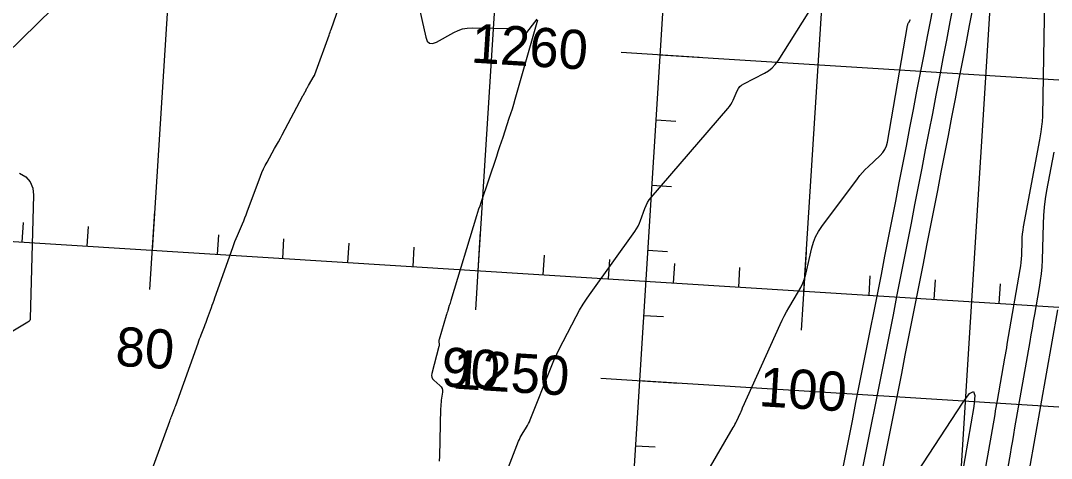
# Model space of a CAD drawing. Extents: x 658976 to 668721, y 639543 to 647196.
# Drawn here: x 661529.7 to 661687.6, y 641890.7 to 641957.7 of the extents above; entities that cross this region are included whole.
import ezdxf

# ---------------------------------------------------------------- set-up
doc = ezdxf.new("R2010")
doc.units = 0
for name, color, linetype in [('Ex_Minor Contours', 7, 'Continuous'), ('R_Axis', 7, 'Continuous'), ('R_Axis Annot', 7, 'Continuous'), ('R_Grid', 7, 'Continuous'), ('R_Water', 7, 'Continuous')]:
    doc.layers.add(name, color=color, linetype=linetype)

msp = doc.modelspace()

# ---------------------------------------------------------------- linework, layer by layer
at = {"layer": 'Ex_Minor Contours'}
for points in [[(661686.69, 641967.13), (661686.26, 641943.13), (661686.25, 641942.82), (661686.23, 641942.51), (661686.2, 641942.21), (661686.16, 641941.9), (661685.99, 641940.68), (661685.94, 641940.38), (661685.89, 641940.07), (661685.84, 641939.77), (661685.79, 641939.47), (661683.33, 641926.15), (661683.24, 641925.61), (661683.17, 641925.07), (661683.12, 641924.52), (661683.1, 641923.97), (661683.03, 641921.78), (661683, 641921.23), (661682.96, 641920.68), (661682.89, 641920.14), (661682.81, 641919.6), (661680.82, 641908.15), (661680.73, 641907.61), (661680.64, 641907.08), (661680.54, 641906.54), (661680.45, 641906.01), (661679.31, 641899.55), (661679.22, 641899.01), (661679.12, 641898.47), (661679.03, 641897.93), (661678.94, 641897.38), (661677.04, 641886.44)], [(661589.69, 641964.5), (661591.78, 641955.18), (661592, 641954.58), (661592.35, 641954.26), (661592.83, 641954.21), (661593.42, 641954.44), (661596.06, 641955.9), (661596.73, 641956.22), (661597.42, 641956.44), (661598.14, 641956.57), (661598.88, 641956.61), (661605.15, 641956.51), (661605.28, 641956.5), (661605.41, 641956.49), (661605.54, 641956.47), (661605.67, 641956.44), (661606.17, 641956.3), (661606.29, 641956.26), (661606.38, 641956.19), (661606.46, 641956.1), (661606.51, 641955.99), (661606.68, 641955.48), (661606.72, 641955.38), (661606.78, 641955.34), (661606.85, 641955.36), (661606.92, 641955.44), (661608.84, 641957.93)], [(661548.16, 641884.36), (661552.57, 641896.38), (661552.64, 641896.58), (661552.72, 641896.78), (661552.79, 641896.98), (661552.87, 641897.18), (661553.18, 641897.98), (661553.26, 641898.17), (661553.34, 641898.37), (661553.41, 641898.57), (661553.48, 641898.77), (661556.9, 641908.34), (661557.02, 641908.66), (661557.13, 641908.98), (661557.26, 641909.29), (661557.38, 641909.61), (661557.88, 641910.87), (661558, 641911.19), (661558.13, 641911.51), (661558.24, 641911.82), (661558.36, 641912.14), (661558.94, 641913.76), (661559.08, 641914.13), (661559.21, 641914.51), (661559.35, 641914.88), (661559.48, 641915.26), (661562.21, 641922.97), (661562.38, 641923.44), (661562.55, 641923.9), (661562.74, 641924.35), (661562.93, 641924.81), (661563.7, 641926.61), (661563.9, 641927.07), (661564.08, 641927.52), (661564.26, 641927.98), (661564.43, 641928.44), (661566.46, 641933.91), (661566.67, 641934.46), (661566.91, 641935.01), (661567.17, 641935.54), (661567.46, 641936.06), (661568.63, 641938.13), (661568.93, 641938.65), (661569.21, 641939.18), (661569.5, 641939.7), (661569.78, 641940.22), (661572.95, 641946.18), (661572.98, 641946.24), (661573.01, 641946.3), (661573.04, 641946.35), (661573.08, 641946.41), (661573.21, 641946.65), (661573.24, 641946.7), (661573.27, 641946.76), (661573.31, 641946.82), (661573.34, 641946.88), (661573.58, 641947.38), (661573.64, 641947.49), (661573.69, 641947.59), (661573.75, 641947.69), (661573.81, 641947.79), (661574.69, 641949.24), (661574.72, 641949.29), (661574.75, 641949.35), (661574.78, 641949.41), (661574.8, 641949.47), (661576.97, 641955.5), (661577.05, 641955.72), (661577.13, 641955.93), (661577.2, 641956.14), (661577.28, 641956.36), (661578.85, 641960.95)], [(661534.69, 641959.64), (661520.2, 641945.51)], [(661601.78, 641882.44), (661606, 641893.29), (661606.12, 641893.57), (661606.25, 641893.86), (661606.4, 641894.13), (661606.55, 641894.4), (661607.22, 641895.46), (661607.37, 641895.73), (661607.52, 641896), (661607.66, 641896.28), (661607.78, 641896.57), (661611, 641904.66), (661611.41, 641905.66), (661611.85, 641906.65), (661612.32, 641907.62), (661612.81, 641908.59), (661614.83, 641912.42), (661615.35, 641913.37), (661615.9, 641914.3), (661616.49, 641915.21), (661617.1, 641916.1), (661623.8, 641925.43), (661624.07, 641925.83), (661624.31, 641926.25), (661624.52, 641926.68), (661624.7, 641927.13), (661625.35, 641928.97), (661625.53, 641929.42), (661625.75, 641929.84), (661626.01, 641930.25), (661626.31, 641930.63), (661638.06, 641944.26), (661638.31, 641944.56), (661638.52, 641944.88), (661638.71, 641945.21), (661638.88, 641945.56), (661639.5, 641946.99), (661639.67, 641947.32), (661639.9, 641947.61), (661640.17, 641947.86), (661640.5, 641948.06), (661643.68, 641949.68), (661644.29, 641950.05), (661644.84, 641950.49), (661645.33, 641950.99), (661645.75, 641951.57), (661651.21, 641960.26)], [(661608.89, 641957.8), (661605.43, 641945.63), (661605.22, 641944.9), (661605, 641944.17), (661604.77, 641943.44), (661604.53, 641942.71), (661603.57, 641939.81), (661603.33, 641939.09), (661603.09, 641938.37), (661602.84, 641937.64), (661602.6, 641936.92), (661600.21, 641929.82), (661600.04, 641929.32), (661599.88, 641928.83), (661599.72, 641928.33), (661599.57, 641927.83), (661595.63, 641914.86), (661595.57, 641914.66), (661595.51, 641914.47), (661595.45, 641914.28), (661595.39, 641914.08), (661595.15, 641913.31), (661595.09, 641913.12), (661595.03, 641912.92), (661594.97, 641912.73), (661594.91, 641912.54), (661593.81, 641908.88), (661593.79, 641908.79), (661593.78, 641908.7), (661593.77, 641908.62), (661593.78, 641908.53), (661593.82, 641908.17), (661593.83, 641908.08), (661593.82, 641908), (661593.81, 641907.91), (661593.8, 641907.82), (661592.7, 641903.67), (661592.66, 641903.38), (661592.69, 641903.12), (661592.81, 641902.87), (661593, 641902.66), (661593.94, 641901.83), (661594.14, 641901.61), (661594.27, 641901.37), (661594.33, 641901.1), (661594.32, 641900.8), (661594.16, 641899.57), (661594.12, 641899.26), (661594.09, 641898.95), (661594.07, 641898.63), (661594.06, 641898.32), (661593.88, 641891), (661593.84, 641890.26)], [(661632.87, 641885.02), (661638.89, 641895.39), (661639.02, 641895.62), (661639.15, 641895.85), (661639.27, 641896.09), (661639.39, 641896.33), (661640.01, 641897.65), (661640.04, 641897.72), (661640.07, 641897.79), (661640.1, 641897.86), (661640.13, 641897.93), (661640.24, 641898.22), (661640.27, 641898.3), (661640.3, 641898.37), (661640.33, 641898.44), (661640.36, 641898.51), (661646.07, 641911.16), (661646.38, 641911.82), (661646.71, 641912.46), (661647.05, 641913.1), (661647.42, 641913.73), (661648.91, 641916.22), (661649.26, 641916.85), (661649.56, 641917.5), (661649.8, 641918.18), (661649.99, 641918.88), (661650.92, 641922.9), (661651.17, 641923.79), (661651.51, 641924.63), (661651.94, 641925.44), (661652.45, 641926.21), (661657.91, 641933.51), (661658.29, 641934), (661658.7, 641934.47), (661659.12, 641934.92), (661659.57, 641935.35), (661661.39, 641937.05), (661661.8, 641937.5), (661662.12, 641937.99), (661662.36, 641938.53), (661662.51, 641939.12), (661665.59, 641956.98), (661665.61, 641957.1), (661665.65, 641957.22), (661665.7, 641957.34), (661665.77, 641957.45), (661666.04, 641957.88)], [(661688, 641937.59), (661686.9, 641931.68), (661686.7, 641930.42), (661686.54, 641929.15), (661686.42, 641927.88), (661686.36, 641926.61), (661686.19, 641921.05), (661686.14, 641919.99), (661686.05, 641918.95), (661685.93, 641917.9), (661685.76, 641916.86), (661685.04, 641912.7), (661684.86, 641911.67), (661684.68, 641910.63), (661684.5, 641909.59), (661684.32, 641908.55), (661682, 641895.33), (661681.82, 641894.34), (661681.65, 641893.34), (661681.47, 641892.34), (661681.3, 641891.34), (661680.61, 641887.34)], [(661529.55, 641934.37), (661530.5, 641933.78), (661531.17, 641933.02), (661531.56, 641932.08), (661531.67, 641930.97), (661531.19, 641912.12), (661531.16, 641911.93), (661531.1, 641911.77), (661530.99, 641911.63), (661530.84, 641911.52), (661525.89, 641908.64)], [(661684.29, 641888.9), (661688.6, 641913.43)], [(661667.04, 641888.53), (661674.11, 641899.29), (661675.1, 641900.6), (661675.7, 641900.93), (661675.92, 641900.28), (661675.74, 641898.64), (661673.43, 641885.36)]]:
    msp.add_lwpolyline(points, dxfattribs=at)
at = {"layer": 'R_Axis'}
for p, q in [((661621.43, 641852.69), (661637.1, 642102.2)), ((660402.17, 641994.63), (661899.22, 641900.61)), ((661621.71, 641952.87), (661633.69, 641952.12)), ((661627.07, 641942.51), (661630.07, 641942.32)), ((661626.44, 641932.53), (661629.44, 641932.34)), ((661549.53, 641916.56), (661550.28, 641928.53)), ((661529.95, 641923.8), (661530.13, 641926.79)), ((661539.93, 641923.17), (661540.11, 641926.17)), ((661559.89, 641921.92), (661560.07, 641924.91)), ((661569.87, 641921.29), (661570.05, 641924.29)), ((661599.43, 641913.42), (661600.18, 641925.4)), ((661579.85, 641920.66), (661580.04, 641923.66)), ((661589.83, 641920.04), (661590.02, 641923.03)), ((661625.82, 641922.55), (661628.81, 641922.36)), ((661609.79, 641918.78), (661609.98, 641921.78)), ((661619.77, 641918.16), (661619.96, 641921.15)), ((661649.33, 641910.29), (661650.09, 641922.26)), ((661629.75, 641917.53), (661629.94, 641920.52)), ((661639.73, 641916.9), (661639.92, 641919.9)), ((661659.69, 641915.65), (661659.88, 641918.64)), ((661669.67, 641915.02), (661669.86, 641918.02)), ((661679.65, 641914.4), (661679.84, 641917.39)), ((661625.19, 641912.57), (661628.18, 641912.38)), ((661618.58, 641902.97), (661630.55, 641902.21)), ((661623.94, 641892.61), (661626.93, 641892.42))]:
    msp.add_line(p, q, dxfattribs=at)
at = {"layer": 'R_Grid'}
for p, q in [((661549.91, 641922.54), (661562.44, 642122.15)), ((661599.81, 641919.41), (661612.34, 642119.02)), ((661649.71, 641916.28), (661662.25, 642115.88)), ((661621.43, 641852.69), (661637.1, 642102.2)), ((661671.33, 641849.55), (661687, 642099.06)), ((660402.17, 641994.63), (661899.22, 641900.61)), ((661627.7, 641952.49), (663124.75, 641858.47)), ((661624.56, 641902.59), (663121.61, 641808.57))]:
    msp.add_line(p, q, dxfattribs=at)
at = {"layer": 'R_Water'}
for radius in [7576.94, 7579.94, 7582.94]:
    msp.add_arc((654227.01, 643380.77), radius, 348.162318, 349.545226, dxfattribs=at)

# ---------------------------------------------------------------- texts
at = {"layer": 'R_Axis Annot'}
for s, p in [('1260', (661598.61, 641951.31)), ('80', (661544.14, 641904.87)), ('90', (661594.04, 641901.74)), ('1250', (661595.76, 641901.39)), ('100', (661642.71, 641898.68))]:
    msp.add_text(s, height=6, rotation=356.4063, dxfattribs=at).set_placement(p)

doc.saveas('drawing.dxf')
